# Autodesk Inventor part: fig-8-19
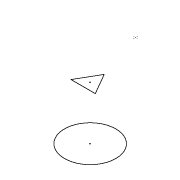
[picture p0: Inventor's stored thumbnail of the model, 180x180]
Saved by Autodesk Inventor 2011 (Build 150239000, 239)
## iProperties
Shininess: 77.0
Angle Display Precision: 2
Document Length Units: 11269
Document Angle Units: 11279
Document Time Units: 11290
Document Mass Units: 11283
Document Length Units Precision: 3
Document Angle Units Precision: 2
Created: 2001-12
Part Number: fig-8-19
Document SubType Name: Modeling
Designer: CADSoft
Density: 1 g/cm^3
Density: 0.0
Volumn: 0.0
Area: 0.0
PropertySet Name: Model Information
Control State: 0
Master: False
Checked Out: False
Author: CADSoft
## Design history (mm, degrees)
workplane "Work Plane3"
workplane "Work Plane4"
sketch "Sketch12"
  geometry: L1 (0, 10.598)-(9.178, -5.299); L2 (9.178, -5.299)-(-9.178, -5.299); L3 (-9.178, -5.299)-(0, 10.598); 1 further point
  constraints: 6 end point, 5 other
workplane "Work Plane5"
sketch "Sketch1"
  geometry: C1 r 19.387 at (0, 0); 1 further point
  constraints: 1 centre point, 1 coincident, 1 other
sketch "Sketch2"
  geometry: 1 further point
